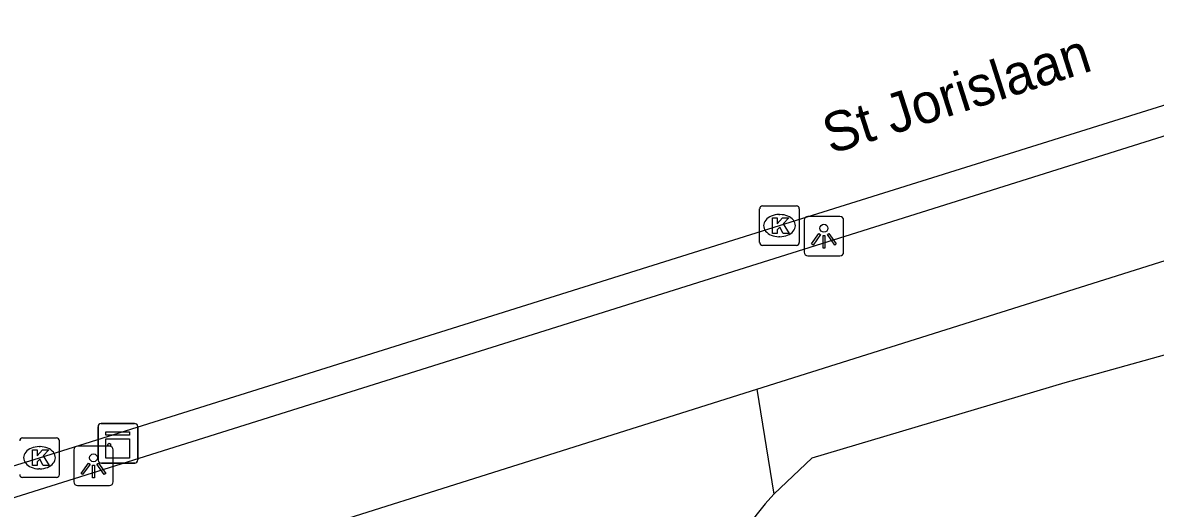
# Model space of a CAD drawing. Extents: x 161882 to 162509, y 381687 to 382379.
# Drawn here: x 161948.92 to 161977.53, y 382332.73 to 382345.01 of the extents above; entities that cross this region are included whole.
import ezdxf

# ---------------------------------------------------------------- set-up
doc = ezdxf.new("R2010")
doc.units = 0
for name, color, linetype in [('IMGEO_Fietspad_open', 7, 'Continuous'), ('IMGEO_Kast', 7, 'Continuous'), ('IMGEO_Kolk', 7, 'Continuous'), ('IMGEO_Lichtpunt', 7, 'Continuous'), ('IMGEO_Openbare_ruimte_label', 7, 'Continuous'), ('IMGEO_Rijbaan_lokaal_gesloten', 7, 'Continuous'), ('IMGEO_Rijbaan_lokaal_open', 7, 'Continuous'), ('IMGEO_Voetpad_open', 7, 'Continuous')]:
    doc.layers.add(name, color=color, linetype=linetype)

msp = doc.modelspace()

# ---------------------------------------------------------------- linework, layer by layer
at = {"layer": 'IMGEO_Fietspad_open'}
for points in [[(161967.462, 382335.743), (162000, 382346.014), (162059.25, 382364.717), (162062.081, 382365.733), (162062.771, 382366.054), (162064.181, 382366.576)], [(161948.301, 382332.881), (162000, 382349.16), (162020.455, 382355.563)]]:
    msp.add_lwpolyline(points, dxfattribs=at)
at = {"layer": 'IMGEO_Kast'}
for p, q in [((161950.83, 382333.953), (161950.83, 382334.794)), ((161950.83, 382334.794), (161950.83, 382333.953)), ((161950.905, 382334.878), (161951.746, 382334.878)), ((161951.746, 382334.878), (161950.905, 382334.878)), ((161951.83, 382334.803), (161951.83, 382333.962)), ((161951.83, 382333.962), (161951.83, 382334.803)), ((161951.755, 382333.878), (161950.914, 382333.878)), ((161950.914, 382333.878), (161951.755, 382333.878))]:
    msp.add_line(p, q, dxfattribs=at)
for points in [[(161951.025, 382334.668), (161951.625, 382334.668), (161951.625, 382334.583), (161951.025, 382334.583), (161951.025, 382334.668)], [(161951.025, 382334.493), (161951.625, 382334.493), (161951.625, 382334.004), (161951.025, 382334.004), (161951.025, 382334.493)]]:
    msp.add_lwpolyline(points, dxfattribs=at)
msp.add_circle((161951.109, 382334.342), 0.0377, dxfattribs=at)
for centre, start, end in [((161950.908, 382334.8), 92.4484, 184.2845), ((161950.908, 382334.8), 92.4484, 184.2845), ((161951.752, 382334.8), 2.4484, 94.2845), ((161951.752, 382334.8), 2.4484, 94.2845), ((161950.908, 382333.956), 182.4484, 274.2845), ((161950.908, 382333.956), 182.4484, 274.2845), ((161951.752, 382333.956), 272.4484, 4.2845), ((161951.752, 382333.956), 272.4484, 4.2845)]:
    msp.add_arc(centre, 0.0779, start, end, dxfattribs=at)
at = {"layer": 'IMGEO_Kolk'}
for p, q in [((161967.61, 382340.38), (161968.462, 382340.38)), ((161967.535, 382339.454), (161967.535, 382340.306)), ((161968.023, 382340.16), (161968.048, 382340.16)), ((161968.536, 382340.306), (161968.536, 382339.454)), ((161968.046, 382339.6), (161968.021, 382339.6)), ((161968.462, 382339.38), (161967.61, 382339.38)), ((161948.924, 382334.514), (161949.776, 382334.514)), ((161949.85, 382334.44), (161949.85, 382333.588)), ((161949.337, 382334.294), (161949.362, 382334.294)), ((161949.776, 382333.514), (161948.924, 382333.514)), ((161949.36, 382333.734), (161949.335, 382333.734))]:
    msp.add_line(p, q, dxfattribs=at)
for points in [[(161967.61, 382340.38), (161968.462, 382340.38)], [(161967.535, 382339.454), (161967.535, 382340.306)], [(161967.856, 382340.08), (161967.979, 382340.08), (161967.979, 382339.929), (161968.109, 382340.08), (161968.273, 382340.08), (161968.127, 382339.929), (161968.28, 382339.68), (161968.128, 382339.68), (161968.043, 382339.844), (161967.979, 382339.777), (161967.979, 382339.68), (161967.856, 382339.68), (161967.856, 382340.08)], [(161968.536, 382340.306), (161968.536, 382339.454)], [(161968.462, 382339.38), (161967.61, 382339.38)], [(161948.924, 382334.514), (161949.776, 382334.514)], [(161949.85, 382334.44), (161949.85, 382333.588)], [(161949.17, 382334.214), (161949.293, 382334.214), (161949.293, 382334.063), (161949.423, 382334.214), (161949.587, 382334.214), (161949.441, 382334.063), (161949.594, 382333.814), (161949.442, 382333.814), (161949.357, 382333.978), (161949.293, 382333.911), (161949.293, 382333.814), (161949.17, 382333.814), (161949.17, 382334.214)], [(161949.776, 382333.514), (161948.924, 382333.514)]]:
    msp.add_lwpolyline(points, dxfattribs=at)
for centre, start, end in [((161967.612, 382340.304), 91.552, 178.448), ((161967.612, 382340.304), 91.552, 178.448), ((161968.46, 382340.304), 1.552, 88.448), ((161968.46, 382340.304), 1.552, 88.448), ((161967.612, 382339.456), 181.552, 268.448), ((161967.612, 382339.456), 181.552, 268.448), ((161968.46, 382339.456), 271.552, 358.448), ((161968.46, 382339.456), 271.552, 358.448), ((161948.926, 382334.438), 91.552, 178.448), ((161948.926, 382334.438), 91.552, 178.448), ((161949.774, 382334.438), 1.552, 88.448), ((161949.774, 382334.438), 1.552, 88.448), ((161948.926, 382333.59), 181.552, 268.448), ((161948.926, 382333.59), 181.552, 268.448), ((161949.774, 382333.59), 271.552, 358.448), ((161949.774, 382333.59), 271.552, 358.448)]:
    msp.add_arc(centre, 0.0765, start, end, dxfattribs=at)
for centre, major_axis, ratio, start_param, end_param in [((161968.022, 382339.88), (-0.387, 0.002), 0.722429, 4.712389, 7.853982), ((161968.047, 382339.88), (-0.39, 0.002), 0.717154, 1.570796, 4.712389), ((161949.336, 382334.014), (-0.387, 0.002), 0.722429, 4.712389, 7.853982), ((161949.361, 382334.014), (-0.39, 0.002), 0.717154, 1.570796, 4.712389)]:
    msp.add_ellipse(centre, major_axis=major_axis, ratio=ratio, start_param=start_param, end_param=end_param, dxfattribs=at)
at = {"layer": 'IMGEO_Lichtpunt'}
for p, q in [((161969.561, 382340.111), (161968.753, 382340.111)), ((161969.561, 382340.111), (161968.753, 382340.111)), ((161968.659, 382340.016), (161968.659, 382339.209)), ((161968.659, 382340.016), (161968.659, 382339.209)), ((161969.655, 382339.209), (161969.655, 382340.016)), ((161969.655, 382339.209), (161969.655, 382340.016)), ((161968.753, 382339.115), (161969.561, 382339.115)), ((161968.753, 382339.115), (161969.561, 382339.115)), ((161950.214, 382334.213), (161950.214, 382333.406)), ((161950.214, 382334.213), (161950.214, 382333.406)), ((161951.116, 382334.308), (161950.308, 382334.308)), ((161951.116, 382334.308), (161950.308, 382334.308)), ((161951.21, 382333.406), (161951.21, 382334.213)), ((161951.21, 382333.406), (161951.21, 382334.213)), ((161950.308, 382333.312), (161951.116, 382333.312)), ((161950.308, 382333.312), (161951.116, 382333.312))]:
    msp.add_line(p, q, dxfattribs=at)
for points in [[(161969.033, 382339.68), (161969.072, 382339.652), (161968.884, 382339.39), (161968.846, 382339.417), (161969.033, 382339.68)], [(161969.135, 382339.632), (161969.182, 382339.632), (161969.182, 382339.31), (161969.135, 382339.31), (161969.135, 382339.632)], [(161969.245, 382339.652), (161969.283, 382339.679), (161969.47, 382339.417), (161969.431, 382339.389), (161969.245, 382339.652)], [(161950.588, 382333.877), (161950.627, 382333.849), (161950.439, 382333.587), (161950.401, 382333.614), (161950.588, 382333.877)], [(161950.69, 382333.829), (161950.737, 382333.829), (161950.737, 382333.507), (161950.69, 382333.507), (161950.69, 382333.829)], [(161950.8, 382333.849), (161950.838, 382333.876), (161951.025, 382333.614), (161950.986, 382333.586), (161950.8, 382333.849)]]:
    msp.add_lwpolyline(points, dxfattribs=at)
for centre in [(161969.158, 382339.814), (161950.713, 382334.011)]:
    msp.add_circle(centre, 0.0994, dxfattribs=at)
for centre, start, end in [((161968.753, 382340.016), 90, 180), ((161968.753, 382340.016), 90, 180), ((161969.561, 382340.016), 0, 90), ((161969.561, 382340.016), 0, 90), ((161968.753, 382339.209), 180, 270), ((161968.753, 382339.209), 180, 270), ((161969.561, 382339.209), 270, 0), ((161969.561, 382339.209), 270, 360), ((161950.308, 382334.213), 90, 180), ((161950.308, 382334.213), 90, 180), ((161951.116, 382334.213), 0, 90), ((161951.116, 382334.213), 0, 90), ((161950.308, 382333.406), 180, 270), ((161950.308, 382333.406), 180, 270), ((161951.116, 382333.406), 270, 0), ((161951.116, 382333.406), 270, 360)]:
    msp.add_arc(centre, 0.0946, start, end, dxfattribs=at)
at = {"layer": 'IMGEO_Rijbaan_lokaal_gesloten'}
msp.add_lwpolyline([(161948.083, 382333.626), (161949.35, 382334.014), (161968.036, 382339.881), (161983.822, 382344.825), (161995.55, 382348.55), (162000, 382350.162), (162000.258, 382350.255), (162002.543, 382351.186), (162009.839, 382354.536)], dxfattribs=at)
at = {"layer": 'IMGEO_Rijbaan_lokaal_open'}
for points in [[(161914.427, 382315.439), (161915.414, 382316.001), (161919.334, 382317.605), (161948.012, 382329.444), (161949.541, 382330.086), (161967.462, 382335.743)], [(161967.462, 382335.743), (161967.89, 382333.094)]]:
    msp.add_lwpolyline(points, dxfattribs=at)
msp.add_arc((161974.387, 382327.173), 8.79, 137.6569, 203.858, dxfattribs=at)
at = {"layer": 'IMGEO_Voetpad_open'}
msp.add_lwpolyline([(161967.89, 382333.094), (161968.862, 382334.009), (161975.252, 382335.913), (162000, 382342.816), (162003.763, 382343.866)], dxfattribs=at)

# ---------------------------------------------------------------- texts
at = {"layer": 'IMGEO_Openbare_ruimte_label'}
msp.add_text('St Jorislaan', height=1, rotation=17.7643, dxfattribs=at).set_placement((161969.326, 382341.679))

doc.saveas('drawing.dxf')
